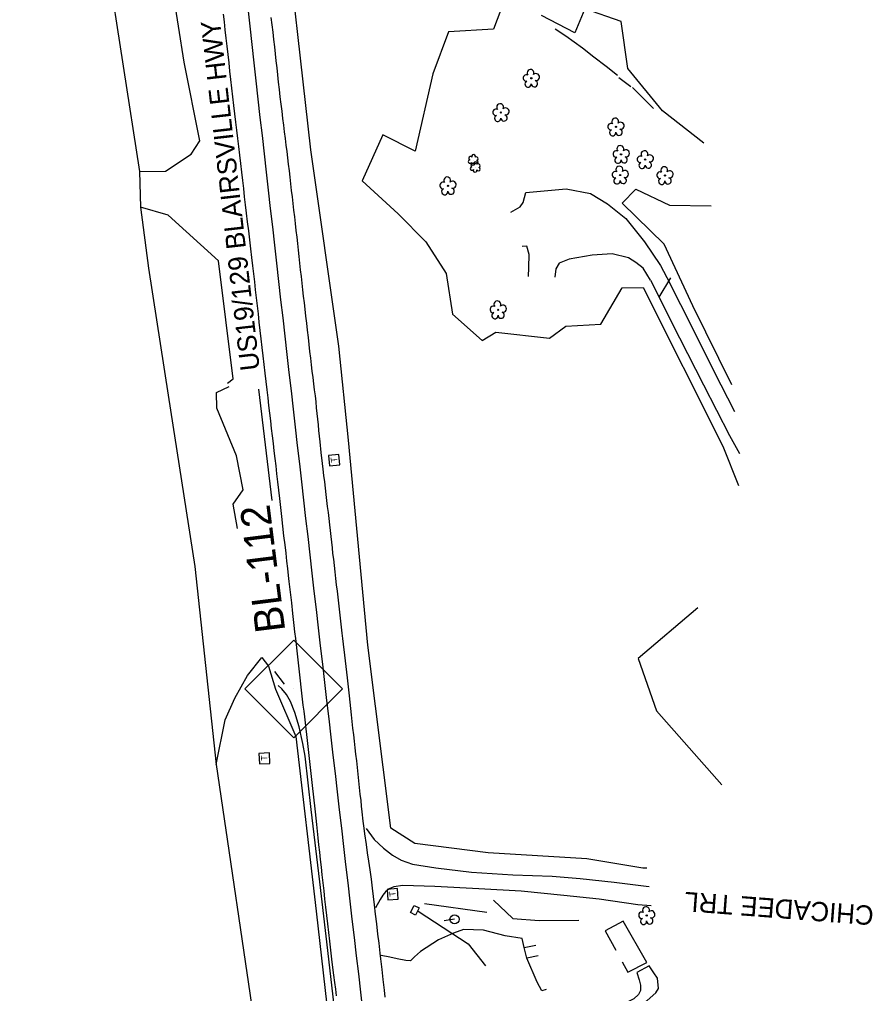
# Model space of a CAD drawing. Extents: x 476627 to 479509, y 495837 to 499842.
# Drawn here: x 477899 to 478358, y 497870 to 498393 of the extents above; entities that cross this region are included whole.
import ezdxf

# ---------------------------------------------------------------- set-up
doc = ezdxf.new("R2010")
doc.units = 0
for name, color, linetype in [('CTL Secondary Horizontal and Vertical CELL', 7, 'Continuous'), ('CTL Secondary Horizontal and Vertical Text', 7, 'Continuous'), ('Exist Guardrail', 7, 'Continuous'), ('Exist Horizontal Alignment', 7, 'Continuous'), ('Exist Other Culture Area Outline', 7, 'Continuous'), ('Exist Other Culture Fence Line', 7, 'Continuous'), ('Exist Other Culture Gate', 7, 'Continuous'), ('Exist Other Culture Sign', 7, 'Continuous'), ('Exist Roads EOP', 7, 'Continuous'), ('Exist Roads EOP Other', 7, 'Continuous'), ('Exist Roads EOP Other Leader', 7, 'Continuous'), ('Exist Roads EOP Text', 7, 'Continuous'), ('Exist Roads Soil', 7, 'Continuous'), ('Exist Roads Soil Text', 7, 'Continuous'), ('Exist Utilities Power Pole CELL', 7, 'Continuous'), ('Exist Utilities Telephone Pedestal CELL', 7, 'Continuous'), ('Exist Vegetation Hedge Row', 7, 'Continuous'), ('Exist Vegetation Shrub CELL', 7, 'Continuous'), ('Exist Vegetation Tree CELL', 7, 'Continuous'), ('Exist Vegetation Woods Line', 7, 'Continuous')]:
    doc.layers.add(name, color=color, linetype=linetype)

msp = doc.modelspace()

# ---------------------------------------------------------------- linework, layer by layer
at = {"layer": 'CTL Secondary Horizontal and Vertical CELL'}
msp.add_line((478046.72, 498033.28), (478046.72, 498033.28), dxfattribs=at)
msp.add_lwpolyline([(478020.65, 498033.37), (478046.85, 498059.57), (478073.1, 498033.32), (478046.9, 498007.11)], close=True, dxfattribs=at)
at = {"layer": 'Exist Guardrail'}
msp.add_lwpolyline([(478086.46, 497676.11), (478082.96, 497723.06), (478079.76, 497760.55), (478076.82, 497789.03), (478072.71, 497825.54), (478068.52, 497863.08), (478065.12, 497892.72), (478060.78, 497929.66), (478056.27, 497968.59), (478052.93, 497997.1), (478051.65, 498003.96), (478049.7, 498012.85), (478047.39, 498020.65), (478045.09, 498026.62), (478042.93, 498030.39), (478040.52, 498033.29), (478038.53, 498035.24)], dxfattribs=at)
at = {"layer": 'Exist Horizontal Alignment'}
msp.add_arc((592937.27, 511299.31), 115636.96, 186.405023, 186.7177067, dxfattribs=at)
at = {"layer": 'Exist Other Culture Area Outline'}
for p, q in [((478228.04, 498356.92), (478221.56, 498361.85)), ((478240.25, 498345.23), (478228.95, 498356.67)), ((478178.15, 497889.93), (478172.1, 497888.53))]:
    msp.add_line(p, q, dxfattribs=at)
for points in [[(478220.77, 498362.97), (478214.77, 498367.82), (478208.19, 498372.93), (478201.95, 498377.66), (478193.13, 498384.2), (478187.39, 498387.93)], [(478223.32, 497886.57), (478226.34, 497880.98), (478236.58, 497886.28), (478223.9, 497908.56), (478214.25, 497903.35)], [(478214.25, 497903.35), (478219.92, 497892.85)], [(478172.1, 497888.53), (478170.7, 497894.31), (478176.94, 497895.56)]]:
    msp.add_lwpolyline(points, dxfattribs=at)
at = {"layer": 'Exist Other Culture Fence Line'}
msp.add_line((478117.07, 497917.91), (478150.62, 497913.26), dxfattribs=at)
msp.add_lwpolyline([(478164.59, 497909.88), (478178.69, 497908.79), (478200.08, 497909.02)], dxfattribs=at)
at = {"layer": 'Exist Other Culture Gate'}
for p, q in [((478249.31, 498254.26), (478242.99, 498243.9)), ((478164.59, 497909.88), (478154.18, 497919.8))]:
    msp.add_line(p, q, dxfattribs=at)
at = {"layer": 'Exist Other Culture Sign'}
msp.add_line((478041.83, 498035.91), (478036.68, 498042.65), dxfattribs=at)
at = {"layer": 'Exist Roads EOP'}
for points in [[(478069.81, 497868.39), (478069.39, 497871.86), (478068.93, 497875.52), (478068.44, 497879.42), (478067.92, 497883.6), (478067.37, 497888.06), (478066.79, 497892.82), (478066.21, 497897.66), (478065.65, 497902.39), (478065.12, 497907.01), (478064.61, 497911.52), (478064.12, 497915.96), (478063.63, 497920.36), (478063.14, 497924.74), (478062.65, 497929.08), (478062.18, 497933.36), (478061.71, 497937.54), (478061.27, 497941.61), (478060.83, 497945.58), (478060.41, 497949.45), (478060.01, 497953.21), (478059.61, 497956.87), (478059.23, 497960.42), (478058.87, 497963.87), (478058.51, 497967.22), (478058.16, 497970.46), (478057.83, 497973.59), (478057.5, 497976.68), (478057.16, 497979.82), (478056.81, 497982.99), (478056.45, 497986.21), (478056.09, 497989.44), (478055.73, 497992.68), (478055.37, 497995.91), (478055, 497999.15), (478054.63, 498002.38), (478054.26, 498005.58), (478053.89, 498008.77), (478053.51, 498011.93), (478053.13, 498015.08), (478052.75, 498018.25), (478052.37, 498021.41), (478051.98, 498024.59), (478051.6, 498027.79), (478051.22, 498031.02), (478050.84, 498034.29), (478050.47, 498037.59), (478050.1, 498040.89), (478049.74, 498044.16), (478049.37, 498047.4), (478049.02, 498050.6), (478048.66, 498053.82), (478048.29, 498057.12), (478047.91, 498060.5), (478047.52, 498063.96), (478047.13, 498067.38), (478046.76, 498070.66), (478046.4, 498073.78), (478045.74, 498079.65), (478045.09, 498085.32), (478044.42, 498091.05), (478044.04, 498094.34), (478043.63, 498097.98), (478043.18, 498101.96), (478042.69, 498106.25), (478042.17, 498110.82), (478041.61, 498115.66), (478041.02, 498120.78), (478040.43, 498125.93), (478039.86, 498130.89), (478039.32, 498135.66), (478038.81, 498140.23), (478038.31, 498144.65), (478037.83, 498148.95), (478037.35, 498153.15), (478036.88, 498157.24), (478036.41, 498161.27), (478035.93, 498165.3), (478035.46, 498169.34), (478034.98, 498173.37), (478034.5, 498177.43), (478034.01, 498181.53), (478033.53, 498185.67), (478033.04, 498189.84), (478032.54, 498194.1), (478032.02, 498198.48), (478031.49, 498202.98), (478030.94, 498207.61), (478030.39, 498212.28), (478029.86, 498216.9), (478029.34, 498221.47), (478028.84, 498226.01), (478028.35, 498230.48), (478027.86, 498234.89), (478027.36, 498239.23), (478026.87, 498243.51), (478026.37, 498247.77), (478025.87, 498252.08), (478025.36, 498256.43), (478024.85, 498260.82), (478024.32, 498265.29), (478023.78, 498269.89), (478023.22, 498274.62), (478022.64, 498279.47), (478022.06, 498284.31), (478021.5, 498288.99), (478020.97, 498293.52), (478020.45, 498297.89), (478019.94, 498302.22), (478019.43, 498306.63), (478018.91, 498311.13), (478018.39, 498315.71), (478017.87, 498320.29), (478017.35, 498324.8), (478016.83, 498329.24), (478016.32, 498333.61), (478015.8, 498337.98), (478015.27, 498342.44), (478014.73, 498346.97), (478014.19, 498351.59), (478013.64, 498356.23), (478013.11, 498360.82), (478012.59, 498365.37), (478012.08, 498369.88), (478011.58, 498374.35), (478011.08, 498378.78), (478010.57, 498383.17), (478010.06, 498387.53), (478009.56, 498391.82), (478009.06, 498396.03)], [(478096.04, 497867.6), (478095.58, 497871.4), (478094.93, 497877.04), (478094.34, 497882.55), (478093.69, 497888.28), (478093.33, 497891.3), (478092.69, 497896.61), (478092.08, 497901.54), (478091.42, 497906.96), (478090.81, 497912.22), (478090.25, 497917.18), (478089.74, 497921.72), (478089.2, 497926.24), (478088.55, 497931.14), (478087.85, 497936.08), (478087.19, 497940.73), (478086.55, 497945.23), (478085.92, 497949.73), (478085.12, 497955.47), (478084.7, 497958.45), (478084.23, 497962.32), (478083.67, 497967.33), (478083.35, 497970.23), (478083, 497973.39), (478082.63, 497976.81), (478082.24, 497980.37), (478081.85, 497983.94), (478081.46, 497987.51), (478081.06, 497991.09), (478080.67, 497994.65), (478080.27, 497998.2), (478079.86, 498001.71), (478079.46, 498005.21), (478079.06, 498008.7), (478078.67, 498012.21), (478078.29, 498015.75), (478077.92, 498019.32), (478077.55, 498022.85), (478077.19, 498026.28), (478076.82, 498029.63), (478076.45, 498032.88), (478076.08, 498036.06), (478075.71, 498039.21), (478075.35, 498042.33), (478074.99, 498045.42), (478074.64, 498048.47), (478074.29, 498051.48), (478073.59, 498057.38), (478073.24, 498060.33), (478072.88, 498063.36), (478072.51, 498066.47), (478072.13, 498069.67), (478071.75, 498072.91), (478071.38, 498076.14), (478071.02, 498079.37), (478070.66, 498082.61), (478070.29, 498085.88), (478069.91, 498089.24), (478069.52, 498092.67), (478069.11, 498096.19), (478068.7, 498099.67), (478068.31, 498103), (478067.94, 498106.18), (478067.6, 498109.2), (478067.26, 498112.18), (478066.92, 498115.24), (478066.56, 498118.38), (478066.19, 498121.58), (478065.82, 498124.83), (478065.44, 498128.08), (478065.06, 498131.34), (478064.68, 498134.6), (478064.29, 498137.89), (478063.9, 498141.22), (478063.49, 498144.59), (478063.08, 498148), (478062.68, 498151.35), (478062.31, 498154.54), (478061.67, 498160.41), (478061.07, 498166.12), (478060.75, 498169.09), (478060.42, 498172.14), (478060.1, 498175.23), (478059.77, 498178.32), (478059.45, 498181.41), (478059.14, 498184.49), (478058.81, 498187.6), (478058.46, 498190.77), (478058.08, 498194), (478057.66, 498197.28), (478057.24, 498200.63), (478056.82, 498204.04), (478056.4, 498207.53), (478055.98, 498211.08), (478055.56, 498214.71), (478055.13, 498218.42), (478054.7, 498222.21), (478054.26, 498226.09), (478053.82, 498229.96), (478053.39, 498233.71), (478052.96, 498237.35), (478052.54, 498240.89), (478052.13, 498244.38), (478051.72, 498247.9), (478051.32, 498251.46), (478050.93, 498255.05), (478050.55, 498258.63), (478050.16, 498262.18), (478049.78, 498265.69), (478049.4, 498269.17), (478049.02, 498272.66), (478048.62, 498276.19), (478048.22, 498279.77), (478047.81, 498283.41), (478047.39, 498287.05), (478046.97, 498290.65), (478046.54, 498294.23), (478046.12, 498297.77), (478045.7, 498301.29), (478045.29, 498304.8), (478044.89, 498308.32), (478044.5, 498311.83), (478044.1, 498315.33), (478043.7, 498318.81), (478043.27, 498322.26), (478042.84, 498325.68), (478042.39, 498329.13), (478041.94, 498332.67), (478041.48, 498336.3), (478041.01, 498340), (478040.55, 498343.78), (478040.08, 498347.63), (478039.62, 498351.55), (478039.16, 498355.52), (478038.71, 498359.49), (478038.28, 498363.38), (478037.86, 498367.18), (478037.46, 498370.91), (478037.05, 498374.63), (478036.63, 498378.44), (478036.18, 498382.33), (478035.72, 498386.31), (478035.26, 498390.31), (478034.8, 498394.27)]]:
    msp.add_lwpolyline(points, dxfattribs=at)
at = {"layer": 'Exist Roads EOP Other'}
msp.add_line((478109.57, 497913.05), (478111.52, 497916.99), dxfattribs=at)
msp.add_lwpolyline([(478111.52, 497916.99), (478114.17, 497915.68), (478112.29, 497911.7), (478109.57, 497913.05)], dxfattribs=at)
at = {"layer": 'Exist Roads EOP Other Leader'}
msp.add_lwpolyline([(478113.68, 497913.88), (478140.55, 497896.27), (478149.85, 497884.54)], dxfattribs=at)
at = {"layer": 'Exist Roads Soil'}
for points in [[(478163.47, 498289.61), (478168.6, 498292.36), (478170.14, 498294.69), (478171.52, 498300.13), (478193.29, 498302.17), (478206.25, 498299.7), (478215.44, 498294.1), (478225.31, 498286.18), (478235.26, 498273.57), (478244.03, 498260.93), (478248.88, 498251.41)], [(478173.09, 498255.06), (478173.2, 498259.88), (478173.43, 498266.87), (478172.03, 498271.38), (478169.68, 498271.15)], [(478238.51, 498253.07), (478234.58, 498259.4), (478230.77, 498262.48), (478226.76, 498265), (478217.88, 498267.13), (478207.29, 498266.51), (478194.84, 498264.39), (478189.53, 498262.21), (478187.77, 498259.17), (478187.13, 498254.7)], [(478238.51, 498253.07), (478254.15, 498222.08), (478267.08, 498196.73), (478280.99, 498169.5), (478286.44, 498159.89)], [(478283.85, 498182.31), (478272.7, 498203.91), (478260.79, 498228.06), (478248.88, 498251.41)], [(478085.72, 497958.35), (478090, 497952.42), (478095.16, 497947.63), (478099.84, 497944.03), (478104.59, 497941.34), (478110.66, 497939.15), (478123.23, 497937.11), (478142.46, 497934.84), (478164.52, 497933.38), (478185.64, 497932.68), (478200.76, 497931.38), (478219.11, 497929.44), (478236.15, 497927.21), (478237.79, 497927.06)], [(478238.98, 497916.73), (478231.76, 497917.27), (478211.06, 497920.25), (478192.06, 497922.33), (478169.07, 497924.67), (478146.37, 497925.91), (478122.71, 497927.12), (478105.41, 497927.64), (478100.61, 497926.95), (478098.06, 497925.84), (478096.08, 497924.2), (478094.67, 497922.38), (478093.23, 497920.14), (478090.82, 497915.61)], [(478170.7, 497894.31), (478169.54, 497899.2), (478160.44, 497900.65), (478148.8, 497903.72), (478138.04, 497904.02), (478132.66, 497901.95), (478124.59, 497898.51), (478115.03, 497892.16), (478111.81, 497889.22), (478109.65, 497887.12), (478107.16, 497887.32), (478102.42, 497888.24), (478098.57, 497889.16), (478093.81, 497890.06)], [(478182.53, 497871.69), (478180.1, 497871.05), (478177.68, 497875.7), (478172.1, 497888.53)], [(478186.79, 497833.73), (478198.04, 497844.42), (478205.11, 497850.12), (478224.08, 497858.1), (478236.7, 497865.83), (478241.46, 497869.88), (478242.83, 497872.32), (478242.26, 497877.8), (478240.27, 497880.71), (478237.86, 497884.4), (478231.22, 497880.88), (478232.53, 497876.89), (478233.19, 497874), (478233.15, 497871.19), (478232.08, 497869.02), (478229.65, 497866.7), (478215.95, 497859.69), (478202.54, 497854.7), (478192.27, 497852.52), (478188.79, 497852.84), (478187.2, 497853.84), (478185.72, 497856.99), (478186.63, 497857.46)]]:
    msp.add_lwpolyline(points, dxfattribs=at)
at = {"layer": 'Exist Utilities Power Pole CELL'}
for q in [(478127.7, 497908.71), (478133.27, 497909.47)]:
    msp.add_line((478133.27, 497909.47), q, dxfattribs=at)
msp.add_circle((478133.27, 497909.47), 2.45, dxfattribs=at)
at = {"layer": 'Exist Utilities Telephone Pedestal CELL'}
for p, q in [((478068.52, 498156.17), (478068.52, 498156.17)), ((478031.04, 497995.91), (478031.04, 497995.91)), ((478100, 497922.87), (478100, 497922.87))]:
    msp.add_line(p, q, dxfattribs=at)
for points in [[(478071.58, 498153.71), (478071.08, 498159.28), (478065.51, 498158.79), (478066.01, 498153.21), (478071.58, 498153.71)], [(478033.97, 497993.3), (478033.75, 497998.89), (478028.16, 497998.67), (478028.38, 497993.08), (478033.97, 497993.3)], [(478103.03, 497920.37), (478102.61, 497925.95), (478097.03, 497925.53), (478097.45, 497919.95), (478103.03, 497920.37)]]:
    msp.add_lwpolyline(points, dxfattribs=at)
at = {"layer": 'Exist Vegetation Hedge Row'}
for points in [[(477963.92, 498311.35), (477977.85, 498311.67), (477991.77, 498320.81), (477996.36, 498327.92), (477987.9, 498370.28), (477978.86, 498428.47), (477975.53, 498495.68), (477961.52, 498510.8), (477950.56, 498529.32), (477945.43, 498576.07), (477942.36, 498628.75), (477934.97, 498665.8), (477920.5, 498695.73), (477916.85, 498708.28)], [(478011.2, 498197.74), (478014.32, 498200.06), (478006.41, 498263.42), (477979.43, 498287.88), (477964.48, 498292.29)], [(478016.68, 498119.62), (478014.36, 498132.7), (478019.59, 498140.39), (478016.03, 498158.61), (478005.47, 498184.27), (478005.36, 498192.67), (478012.09, 498195.89)], [(478027.98, 498194.35), (478035, 498134.68)], [(478005.17, 497992.72), (478010.05, 498016.72), (478015.24, 498028.27), (478022.07, 498040.55), (478029.76, 498050.13), (478033.34, 498045.53), (478037.13, 498033.15), (478047.9, 498007.71), (478058.84, 497913.8), (478070.21, 497814.5), (478081.44, 497692.59)]]:
    msp.add_lwpolyline(points, dxfattribs=at)
at = {"layer": 'Exist Vegetation Shrub CELL'}
for p, q in [((478143.33, 498317.47), (478143.33, 498317.47)), ((478144.43, 498313.68), (478144.43, 498313.68))]:
    msp.add_line(p, q, dxfattribs=at)
for centre, radius, start, end in [((478141.53, 498316.77), 0.955, 95.1099, 327.9534), ((478141.85, 498318.6), 0.968, 35.8908, 245.4216), ((478142.95, 498314.81), 0.968, 35.8908, 245.4216), ((478143.2, 498315.79), 0.984, 151.2797, 21.387), ((478143.56, 498319.51), 0.99, 334.8391, 200.4717), ((478144.66, 498315.72), 0.99, 334.8391, 200.4717), ((478144.97, 498316.54), 0.937, 204.9913, 73.4601), ((478145, 498318.34), 0.929, 284.4567, 126.0861), ((478142.63, 498312.97), 0.955, 95.1099, 327.9534), ((478144.3, 498311.99), 0.984, 151.2797, 21.387), ((478146.07, 498312.75), 0.937, 204.9913, 73.4601), ((478146.1, 498314.55), 0.929, 284.4567, 126.0861)]:
    msp.add_arc(centre, radius, start, end, dxfattribs=at)
at = {"layer": 'Exist Vegetation Tree CELL'}
for p, q in [((478174.51, 498361.56), (478174.51, 498361.56)), ((478158.15, 498343.13), (478158.15, 498343.13)), ((478220.01, 498335.43), (478220.01, 498335.43)), ((478222.75, 498320.64), (478222.75, 498320.64)), ((478235.72, 498317.84), (478235.72, 498317.84)), ((478222.26, 498309.53), (478222.26, 498309.53)), ((478246.33, 498309.31), (478246.33, 498309.31)), ((478129.71, 498303.76), (478129.71, 498303.76)), ((478156.67, 498237.11), (478156.67, 498237.11)), ((478236.52, 497911.53), (478236.52, 497911.53))]:
    msp.add_line(p, q, dxfattribs=at)
for centre in [(478174.51, 498361.56), (478158.15, 498343.13), (478220.01, 498335.43), (478222.75, 498320.64), (478235.72, 498317.84), (478222.26, 498309.53), (478246.33, 498309.31), (478129.71, 498303.76), (478156.67, 498237.11), (478236.52, 497911.53)]:
    msp.add_circle(centre, 0.326, dxfattribs=at)
for centre, radius, start, end in [((478171.9, 498361.71), 1.73, 62.6636, 279.3457), ((478174.12, 498364.43), 1.86, 330.1651, 219.7134), ((478177.06, 498362.15), 1.9, 257.1011, 134.1999), ((478172.8, 498358.44), 1.69, 111.5671, 6.231), ((478176.18, 498358.66), 1.7, 181.2822, 74.56), ((478157.77, 498346), 1.86, 330.1651, 219.7134), ((478155.55, 498343.28), 1.73, 62.6636, 279.3457), ((478159.83, 498340.23), 1.7, 181.2822, 74.56), ((478160.7, 498343.72), 1.9, 257.1011, 134.1999), ((478156.45, 498340.01), 1.69, 111.5671, 6.231), ((478217.4, 498335.59), 1.73, 62.6636, 279.3457), ((478219.62, 498338.3), 1.86, 330.1651, 219.7134), ((478222.56, 498336.02), 1.9, 257.1011, 134.1999), ((478218.3, 498332.31), 1.69, 111.5671, 6.231), ((478221.68, 498332.53), 1.7, 181.2822, 74.56), ((478220.14, 498320.79), 1.73, 62.6636, 279.3457), ((478222.36, 498323.51), 1.86, 330.1651, 219.7134), ((478225.3, 498321.23), 1.9, 257.1011, 134.1999), ((478235.34, 498320.72), 1.86, 330.1651, 219.7134), ((478221.05, 498317.52), 1.69, 111.5671, 6.231), ((478224.42, 498317.74), 1.7, 181.2822, 74.56), ((478233.12, 498318), 1.73, 62.6636, 279.3457), ((478234.02, 498314.72), 1.69, 111.5671, 6.231), ((478237.39, 498314.94), 1.7, 181.2822, 74.56), ((478238.27, 498318.43), 1.9, 257.1011, 134.1999), ((478219.65, 498309.68), 1.73, 62.6636, 279.3457), ((478221.87, 498312.4), 1.86, 330.1651, 219.7134), ((478224.81, 498310.11), 1.9, 257.1011, 134.1999), ((478243.72, 498309.46), 1.73, 62.6636, 279.3457), ((478245.94, 498312.18), 1.86, 330.1651, 219.7134), ((478248.88, 498309.9), 1.9, 257.1011, 134.1999), ((478127.11, 498303.91), 1.73, 62.6636, 279.3457), ((478129.33, 498306.63), 1.86, 330.1651, 219.7134), ((478132.26, 498304.34), 1.9, 257.1011, 134.1999), ((478220.55, 498306.41), 1.69, 111.5671, 6.231), ((478223.93, 498306.63), 1.7, 181.2822, 74.56), ((478244.63, 498306.19), 1.69, 111.5671, 6.231), ((478248, 498306.41), 1.7, 181.2822, 74.56), ((478128.01, 498300.63), 1.69, 111.5671, 6.231), ((478131.39, 498300.86), 1.7, 181.2822, 74.56), ((478154.06, 498237.26), 1.73, 62.6636, 279.3457), ((478156.28, 498239.98), 1.86, 330.1651, 219.7134), ((478159.22, 498237.7), 1.9, 257.1011, 134.1999), ((478154.96, 498233.99), 1.69, 111.5671, 6.231), ((478158.34, 498234.21), 1.7, 181.2822, 74.56), ((478233.92, 497911.69), 1.73, 62.6636, 279.3457), ((478236.14, 497914.41), 1.86, 330.1651, 219.7134), ((478239.07, 497912.12), 1.9, 257.1011, 134.1999), ((478234.82, 497908.41), 1.69, 111.5671, 6.231), ((478238.19, 497908.63), 1.7, 181.2822, 74.56)]:
    msp.add_arc(centre, radius, start, end, dxfattribs=at)
at = {"layer": 'Exist Vegetation Woods Line'}
for points in [[(478071.03, 498217.47), (478056.11, 498323.15), (478040.82, 498458.32), (478034.94, 498527.74), (478039.59, 498564.51), (478031.67, 498591.42), (478030.01, 498626.63), (478040.61, 498634.33), (478065.91, 498633.36), (478084.75, 498626.27), (478094.83, 498630.37), (478078.73, 498684.72), (478096.71, 498735.02)], [(477899.46, 498701.89), (477918.46, 498604.12), (477927.94, 498530.85), (477937.69, 498486.12), (477946.46, 498424.92), (477963.92, 498311.35), (477964.48, 498292.29), (477968.75, 498259.54), (477979.45, 498191.25)], [(478160.69, 498405.23), (478154.13, 498388.02), (478129.94, 498386.5), (478121.51, 498363.94), (478112.12, 498322.37), (478094.8, 498331.07), (478083.6, 498306.4), (478102.94, 498288.7), (478117.91, 498273.68), (478128.72, 498256.62), (478132.11, 498234.72), (478148.04, 498220.59), (478155.43, 498225.03), (478184.31, 498221.9), (478193.11, 498228.39), (478211.79, 498229.37), (478223.31, 498248.87), (478234.59, 498249.01)], [(478267.21, 498326.66), (478245.06, 498343.99), (478226.38, 498366.89), (478222.86, 498392.1), (478203.2, 498398.8), (478197.95, 498385.96), (478180.07, 498395.32)], [(478282.19, 498196.75), (478261.24, 498239.26), (478245.89, 498272.45), (478223.38, 498294.38), (478230.69, 498301.88), (478248.84, 498293.32), (478271.09, 498292.97)], [(478234.59, 498249.01), (478277.51, 498163.77), (478285.85, 498142.61)], [(478236.65, 497936.88), (478234.46, 497937.05), (478204.31, 497941.97), (478151.3, 497945.16), (478111.98, 497950.15), (478098.99, 497958.5), (478086.64, 498056.86), (478076.3, 498167), (478071.03, 498217.47)], [(477979.45, 498191.25), (477993.64, 498099.1), (478005.17, 497992.72), (478026.78, 497845.41), (478017.87, 497796.88), (478023.44, 497718.17), (478022.43, 497688.31), (478027.96, 497668.21)], [(478264.06, 498076.91), (478231.97, 498049.71), (478241.79, 498021.48), (478276.87, 497981.79)]]:
    msp.add_lwpolyline(points, dxfattribs=at)

# ---------------------------------------------------------------- texts
at = {"layer": 'CTL Secondary Horizontal and Vertical Text'}
msp.add_text('BL-112', height=16, rotation=97.1248, dxfattribs=at).set_placement((478042.33, 498064.57))
at = {"layer": 'Exist Roads EOP Text'}
msp.add_text('US19/129 BLAIRSVILLE HWY', height=10.4, rotation=96.515, dxfattribs=at).set_placement((478028.64, 498204.99))
at = {"layer": 'Exist Roads Soil Text'}
msp.add_text('CHICADEE TRL ', height=10.4, rotation=175.6977, dxfattribs=at).set_placement((478358.85, 497916.61))
at = {"layer": 'Exist Utilities Telephone Pedestal CELL'}
for rotation, p in [(95.0731, (478070.33, 498155.2)), (92.1765, (478032.79, 497994.85)), (94.2983, (478101.8, 497921.87))]:
    msp.add_text('T', height=3.42, rotation=rotation, dxfattribs=at).set_placement(p)

doc.saveas('drawing.dxf')
